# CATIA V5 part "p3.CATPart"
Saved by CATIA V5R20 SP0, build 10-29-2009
Part number: p3
Publications: "Line.1", "Line.2", "Line.3", "Plane.1", "Plane.2"
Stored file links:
  D:\Dropbox\IAO_2011\MMS_GR2\IAO_2011_1439_jlicbarski\p3.CATPart
  D:\Dropbox\IAO_2011\MMS_GR2\IAO_2011_1439_jlicbarski\train.CATProduct

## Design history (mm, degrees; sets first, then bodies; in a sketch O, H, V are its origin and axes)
AxisSystem1: origin (0, 0, 0), X (1, 0, 0), Y (0, 1, 0), Z (0, 0, 1)
Set1
  Point1: linked copy from another document
  Point2: linked copy from another document
Body1 (main body)
  Line1: type PtDir, RefPoint Point1, Direction edge [XY plane of AxisSystem1 | ZX plane of AxisSystem1], Start 0, End 10
  Line2: type PtPt, FirstPoint Point1, SecondPoint Point2
  Line3: type PtDir, RefPoint Point2, Direction edge [XY plane of AxisSystem1 | ZX plane of AxisSystem1], Start 0, End 10
  Plane1: type Normal, Curve Line1
  Plane2: type Normal, Curve Line1, RefPoint Point1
